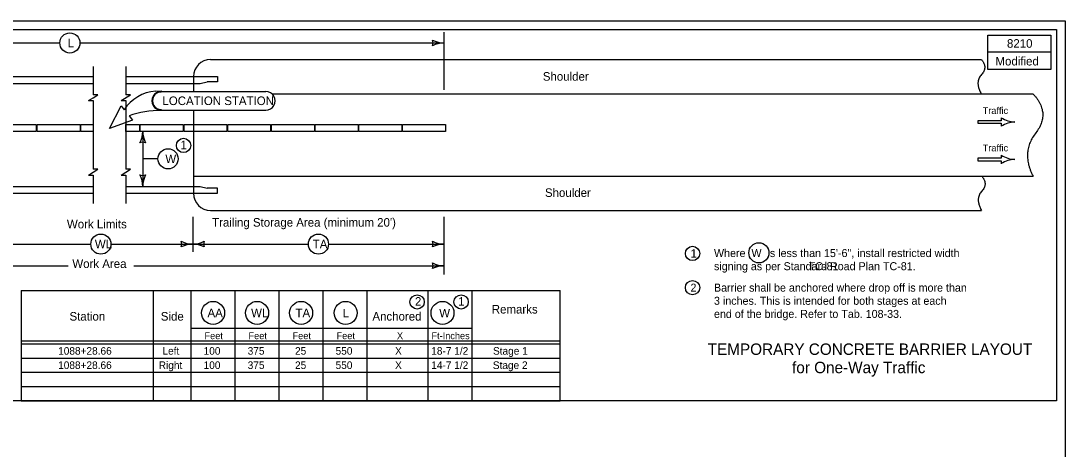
# Model space of a CAD drawing. Extents: x 10133 to 81668, y 7924 to 12229.
# Drawn here: x 15041 to 16868, y 9195 to 9944 of the extents above; entities that cross this region are included whole.
import ezdxf

# ---------------------------------------------------------------- set-up
doc = ezdxf.new("R2010")
doc.units = 0
for name, color, linetype in [('dsnCellsNorthArrow', 7, 'Continuous'), ('Level 10', 7, 'Continuous'), ('Level 11', 7, 'Continuous'), ('Level 2', 7, 'Continuous'), ('Level 22', 7, 'Continuous'), ('Level 63', 7, 'Continuous'), ('Level 8', 7, 'Continuous'), ('Level 9', 7, 'Continuous'), ('SheetBorder', 7, 'Continuous'), ('SheetText', 7, 'Continuous')]:
    doc.layers.add(name, color=color, linetype=linetype)

msp = doc.modelspace()

# ---------------------------------------------------------------- linework, layer by layer
at = {"layer": 'Level 10'}
for p, q in [((16852.5, 9929), (16852.5, 9929)), ((15041.6, 9472), (15041.6, 9279)), ((15041.6, 9472), (15984.1, 9472)), ((15646.6, 9279), (15646.6, 9472)), ((15753.1, 9279), (15753.1, 9472)), ((15830.1, 9279), (15830.1, 9472)), ((15984.1, 9279), (15984.1, 9472))]:
    msp.add_line(p, q, dxfattribs=at)
at = {"layer": 'Level 11'}
for p, q in [((15781, 9924.1), (15781, 9823.2)), ((14230.5, 9905.4), (15109, 9905.4)), ((15144.3, 9905.4), (15781, 9905.4)), ((15167.3, 9864.4), (15167.3, 9814.6)), ((15224.4, 9864.4), (15224.4, 9814.6)), ((15372.7, 9876.4), (16721.1, 9876.4)), ((15021.3, 9846.4), (15167.3, 9846.4)), ((15224.4, 9846.4), (15342.7, 9846.4)), ((15342.7, 9846.4), (15384.7, 9846.4)), ((15342.7, 9846.4), (15342.7, 9820.5)), ((15384.7, 9846.4), (15384.7, 9837.4)), ((15021.3, 9834.4), (15167.3, 9834.4)), ((15224.4, 9834.4), (15342.7, 9834.4)), ((15342.7, 9834.4), (15354.7, 9834.4)), ((15354.7, 9834.4), (15366.7, 9837.4)), ((15384.7, 9837.4), (15366.7, 9837.4)), ((15159.3, 9804.5), (15167.3, 9809.5)), ((15167.3, 9809.5), (15175.3, 9814.6)), ((15175.3, 9814.6), (15167.3, 9814.6)), ((15216.4, 9804.5), (15232.4, 9814.6)), ((15232.4, 9814.6), (15224.4, 9814.6)), ((15276.8, 9821), (15286.3, 9821.4)), ((15286.3, 9821.4), (15286.3, 9819.6)), ((15286.3, 9820.5), (15469.4, 9820.5)), ((15480.2, 9816.4), (16811.5, 9816.4)), ((15159.3, 9804.5), (15167.3, 9804.5)), ((15167.3, 9804.5), (15167.3, 9744.4)), ((15195.9, 9755.5), (15216, 9795.5)), ((15216, 9795.5), (15221.6, 9788.4)), ((15216.4, 9804.5), (15224.4, 9804.5)), ((15224.4, 9804.5), (15224.4, 9744.4)), ((15230.2, 9777.8), (15236.1, 9770.5)), ((15286.3, 9788.9), (15286.3, 9787.1)), ((15286.3, 9788), (15469.4, 9788)), ((15342.7, 9788), (15342.7, 9642.4)), ((16755.8, 9774.5), (16755.8, 9769.3)), ((15236.1, 9770.5), (15195.9, 9755.5)), ((16755.8, 9769.3), (16714.6, 9769.3)), ((16714.6, 9769.3), (16714.6, 9764.8)), ((16714.6, 9764.8), (16755.8, 9764.8)), ((16755.8, 9764.8), (16755.8, 9759.5)), ((16779.8, 9767), (16779.8, 9767)), ((15167.3, 9744.4), (15167.3, 9684.4)), ((15224.4, 9744.4), (15224.4, 9684.4)), ((15254, 9750.7), (15254, 9654.4)), ((15280.6, 9702.6), (15254, 9702.6)), ((16755.8, 9703.8), (16714.6, 9703.8)), ((16714.6, 9703.8), (16714.6, 9699.3)), ((16755.8, 9709.1), (16755.8, 9703.8)), ((16779.8, 9701.6), (16779.8, 9701.6)), ((15167.3, 9679.3), (15175.3, 9684.4)), ((15175.3, 9684.4), (15167.3, 9684.4)), ((15216.4, 9674.3), (15232.4, 9684.4)), ((15232.4, 9684.4), (15224.4, 9684.4)), ((16714.6, 9699.3), (16755.8, 9699.3)), ((16755.8, 9699.3), (16755.8, 9694.1)), ((15159.3, 9674.3), (15167.3, 9679.3)), ((15159.3, 9674.3), (15167.3, 9674.3)), ((15167.3, 9674.3), (15167.3, 9624.4)), ((15216.4, 9674.3), (15224.4, 9674.3)), ((15224.4, 9674.3), (15224.4, 9624.4)), ((15342.7, 9672.4), (16811.5, 9672.4)), ((15021.3, 9654.4), (15167.3, 9654.4)), ((15224.4, 9654.4), (15342.7, 9654.4)), ((15342.7, 9654.4), (15354.7, 9654.4)), ((15354.7, 9654.4), (15366.7, 9651.4)), ((15384.7, 9651.4), (15366.7, 9651.4)), ((15384.7, 9642.4), (15384.7, 9651.4)), ((15021.3, 9642.4), (15167.3, 9642.4)), ((15224.4, 9642.4), (15342.7, 9642.4)), ((15342.7, 9642.4), (15384.7, 9642.4)), ((15372.7, 9612.4), (16721.1, 9612.4)), ((15341.5, 9601.2), (15341.5, 9539.9)), ((15781, 9601.2), (15781, 9500.3)), ((15020.1, 9553.4), (15163.3, 9553.4)), ((15198.3, 9553.4), (15341.5, 9553.4)), ((15211, 9553.4), (15341.5, 9553.4)), ((15341.5, 9553.4), (15543.6, 9553.4)), ((15578.9, 9553.4), (15781, 9553.4)), ((14532.6, 9515.5), (15123.4, 9515.5)), ((15238.7, 9515.5), (15781, 9515.5)), ((15240.1, 9515.5), (15341.5, 9515.5)), ((15272.6, 9279), (15272.6, 9472)), ((15338.6, 9279), (15338.6, 9472)), ((15415.6, 9279), (15415.6, 9472)), ((15492.6, 9279), (15492.6, 9472)), ((15569.6, 9279), (15569.6, 9472)), ((15338.6, 9406.2), (15830.1, 9406.2)), ((15041.6, 9384), (15984.1, 9384)), ((15041.6, 9379), (15984.1, 9379))]:
    msp.add_line(p, q, dxfattribs=at)
for points in [[(14992.8, 9762.7), (15067.8, 9762.7), (15067.8, 9750.7), (14992.8, 9750.7)], [(15069.3, 9762.7), (15144.3, 9762.7), (15144.3, 9750.7), (15069.3, 9750.7)], [(15249.7, 9762.7), (15324.7, 9762.7), (15324.7, 9750.7), (15249.7, 9750.7)], [(15326.2, 9762.7), (15401.2, 9762.7), (15401.2, 9750.7), (15326.2, 9750.7)], [(15402.7, 9762.7), (15477.7, 9762.7), (15477.7, 9750.7), (15402.7, 9750.7)], [(15479.2, 9762.7), (15554.2, 9762.7), (15554.2, 9750.7), (15479.2, 9750.7)], [(15555.7, 9762.7), (15630.7, 9762.7), (15630.7, 9750.7), (15555.7, 9750.7)], [(15632.2, 9762.7), (15707.2, 9762.7), (15707.2, 9750.7), (15632.2, 9750.7)], [(15708.7, 9762.7), (15783.7, 9762.7), (15783.7, 9750.7), (15708.7, 9750.7)]]:
    msp.add_lwpolyline(points, close=True, dxfattribs=at)
for points in [[(15167.3, 9750.7), (15145.8, 9750.7), (15145.8, 9762.7), (15167.3, 9762.7)], [(15167.3, 9762.7), (15167.3, 9750.7)], [(15224.4, 9750.7), (15224.4, 9762.7)], [(15224.4, 9762.7), (15248.2, 9762.7), (15248.2, 9750.7), (15224.4, 9750.7)]]:
    msp.add_lwpolyline(points, dxfattribs=at)
for centre, radius in [((15126.6, 9905.4), 17.6), ((15325.4, 9726), 12.5), ((15298.3, 9702.6), 17.6), ((15180.8, 9553.4), 17.6), ((15561.3, 9553.4), 17.6), ((16331.9, 9538.1), 17.6), ((16331.9, 9538.1), 17.6), ((16215.8, 9537), 12.5), ((16215.8, 9537), 12.5), ((15734, 9452.2), 12.5), ((15811, 9452.2), 12.5), ((15377.1, 9433), 20.1), ((15454.1, 9433), 20.1), ((15531.1, 9433), 20.1), ((15608.9, 9433), 20.1), ((15778.4, 9433), 20.1)]:
    msp.add_circle(centre, radius, dxfattribs=at)
for centre, radius, start, end in [((15745.4, 9905.4), 16.4, 342.2666, 17.7333), ((15781, 9947.9), 42.5, 241.9275, 270), ((15781, 9862.9), 42.5, 90, 118.0725), ((15372.7, 9846.4), 30, 90, 180), ((16781.7, 9815.4), 48.4, 237.618, 267.648), ((16781.7, 9718.7), 48.4, 92.352, 122.382), ((15211.5, 9750.7), 42.5, 331.9275, 0), ((15296.5, 9750.7), 42.5, 180, 208.0725), ((15254, 9715.1), 16.4, 72.2666, 107.7334), ((16781.7, 9749.9), 48.4, 237.618, 267.648), ((16781.7, 9653.3), 48.4, 92.352, 122.382), ((15254, 9690.1), 16.4, 252.2666, 287.7334), ((15211.5, 9654.4), 42.5, 0, 28.0725), ((15296.5, 9654.4), 42.5, 151.9275, 180), ((15372.7, 9642.4), 30, 180, 270), ((15305.9, 9553.4), 16.4, 342.2666, 17.7333), ((15341.5, 9595.9), 42.5, 241.9275, 270), ((15341.5, 9595.9), 42.5, 270, 298.0725), ((15377.1, 9553.4), 16.4, 162.2666, 197.7334), ((15745.4, 9553.4), 16.4, 342.2666, 17.7333), ((15781, 9595.9), 42.5, 241.9275, 270), ((15341.5, 9510.9), 42.5, 90, 118.0725), ((15341.5, 9510.9), 42.5, 61.9275, 90), ((15781, 9510.9), 42.5, 90, 118.0725), ((15745.4, 9515.5), 16.4, 342.2666, 17.7333), ((15781, 9558), 42.5, 241.9275, 270), ((15781, 9473), 42.5, 90, 118.0725)]:
    msp.add_arc(centre, radius, start, end, dxfattribs=at)
for centre, major_axis, start_param, end_param in [((15281.3, 9750.7), (-70.8, 0), 4.776871, 5.71778), ((15286.3, 9804.2), (-16.3, 0), 4.712389, 7.853982), ((15286.3, 9804.2), (15.4, 0), 1.570796, 4.712389), ((15469.4, 9804.2), (16.3, 0), 4.712389, 7.853982), ((15283.5, 9631), (-156.9, 0), 4.694293, 5.059134)]:
    msp.add_ellipse(centre, major_axis=major_axis, ratio=0.995025, start_param=start_param, end_param=end_param, dxfattribs=at)
for points in [[(16721.1, 9876.4), (16732.9, 9862.3), (16709.3, 9837.3), (16720.7, 9816.5)], [(16811.5, 9816.4), (16842.9, 9782), (16789.6, 9714), (16811.5, 9672.4)], [(16721.6, 9672.4), (16733.4, 9658.3), (16709.8, 9633.3), (16721.1, 9612.4)]]:
    msp.add_open_spline(points, degree=2, dxfattribs=at)
at = {"layer": 'Level 22'}
msp.add_lwpolyline([(16842.5, 9919), (16842.5, 9859), (16732.5, 9859), (16732.5, 9919), (16842.5, 9919), (16842.5, 9889), (16732.5, 9889)], dxfattribs=at)
at = {"layer": 'Level 63'}
for p, q in [((15041.6, 9354), (15984.1, 9354)), ((15041.6, 9329), (15984.1, 9329)), ((15041.6, 9304), (15984.1, 9304)), ((15041.6, 9279), (15984.1, 9279))]:
    msp.add_line(p, q, dxfattribs=at)
at = {"layer": 'Level 8'}
for p, q in [((13747.5, 9929), (16852.5, 9929)), ((16852.5, 9929), (16852.5, 9279))]:
    msp.add_line(p, q, dxfattribs=at)
at = {"layer": 'Level 9'}
msp.add_line((16852.5, 9279), (13747.5, 9279), dxfattribs=at)
at = {"layer": 'SheetBorder'}
msp.add_lwpolyline([(13732.5, 9944), (16867.5, 9944), (16867.5, 7924), (13732.5, 7924)], close=True, dxfattribs=at)
at = {"layer": 'SheetText'}
msp.add_circle((16215.8, 9477.2), 12.5, dxfattribs=at)

# ---------------------------------------------------------------- texts
at = {"layer": 'dsnCellsNorthArrow'}
for s, p in [('8210', (16765.8, 9897)), ('Modified', (16745.7, 9866))]:
    msp.add_text(s, height=15, dxfattribs=at).set_placement(p)
at = {"layer": 'Level 2'}
for s, height, p in [('L', 15, (15122.7, 9897.9)), ('Shoulder', 15, (15953.9, 9839.3)), ('LOCATION STATION', 15, (15288.5, 9796.7)), ('Traffic', 12, (16723.3, 9781)), ('1', 15, (15320.1, 9719.5)), ('Traffic', 12, (16723.3, 9715.6)), ('W', 15, (15293.6, 9695.1)), ('Shoulder', 15, (15957.6, 9635.9)), ('Work Limits', 15, (15121.4, 9580.9)), ("Trailing Storage Area (minimum 20')", 15, (15375.4, 9583.9)), ('WL', 15, (15170.3, 9545.9)), ('TA', 15, (15551.4, 9545.9)), ('1', 15, (16212.4, 9529.5)), ('1', 15, (16212.4, 9529.5)), ('Where  W  is less than 15\'-6", install restricted width', 14, (16253.3, 9530.7)), ('Where  W  is less than 15\'-6", install restricted width', 14, (16253.3, 9530.7)), ('Work Area', 15, (15130.9, 9511.6)), ('signing as per Standard Road Plan TC-81.', 14, (16253.3, 9507.7)), ('signing as per Standard Road Plan TC-81.', 14, (16253.3, 9507.7)), ('                                TC-81', 14, (16252.6, 9507.7)), ('                                TC-81', 14, (16252.6, 9507.7)), ('2', 15, (15730.2, 9445.6)), ('1', 15, (15805.8, 9445.6)), ('Remarks', 15, (15864.6, 9431.9)), ('Station', 15, (15125.9, 9419.5)), ('Side', 15, (15285.6, 9419.5)), ('AA', 15, (15367.3, 9425.5)), ('WL', 15, (15443.6, 9425.5)), ('TA', 15, (15521.2, 9425.5)), ('L', 15, (15604, 9425.1)), ('Anchored', 15, (15655.8, 9419.5)), ('W', 15, (15772.7, 9425.1)), ('Feet', 12, (15362.1, 9387)), ('Feet', 12, (15439.1, 9387)), ('Feet', 12, (15516.1, 9387)), ('Feet', 12, (15593.1, 9387)), ('X', 12, (15698.7, 9387)), ('Ft-Inches', 12, (15759.1, 9387))]:
    msp.add_text(s, height=height, dxfattribs=at).set_placement(p)
at = {"layer": 'SheetText'}
for s, height, p in [('2', 14, (16212.2, 9470.2)), ('Barrier shall be anchored where drop off is more than ', 14, (16253.3, 9470.2)), ('3 inches. This is intended for both stages at each ', 14, (16253.3, 9447.2)), ('end of the bridge. Refer to Tab. 108-33.', 14, (16253.3, 9424.2)), ('1088+28.66', 13.2, (15106, 9359.9)), ('Left', 13.2, (15288.5, 9359.9)), ('100', 13.2, (15360.5, 9359.9)), ('375', 13.2, (15437.6, 9359.9)), ('25', 13.2, (15520.4, 9359.9)), ('550', 13.2, (15591.4, 9359.9)), ('X', 13.2, (15695.4, 9359.9)), ('18-7 1/2', 13.2, (15758.7, 9359.9)), ('Stage 1', 13.2, (15866.7, 9359.9)), ('TEMPORARY CONCRETE BARRIER LAYOUT', 20, (16242.3, 9359.5)), ('1088+28.66', 13.2, (15106, 9334.9)), ('Right', 13.2, (15282, 9334.9)), ('100', 13.2, (15360.5, 9334.9)), ('375', 13.2, (15437.6, 9334.9)), ('25', 13.2, (15520.4, 9334.9)), ('550', 13.2, (15591.4, 9334.9)), ('X', 13.2, (15695.4, 9334.9)), ('14-7 1/2', 13.2, (15758.7, 9334.9)), ('Stage 2', 13.2, (15866.4, 9334.9)), ('for One-Way Traffic', 20, (16389.9, 9327.5))]:
    msp.add_text(s, height=height, dxfattribs=at).set_placement(p)

doc.saveas('drawing.dxf')
